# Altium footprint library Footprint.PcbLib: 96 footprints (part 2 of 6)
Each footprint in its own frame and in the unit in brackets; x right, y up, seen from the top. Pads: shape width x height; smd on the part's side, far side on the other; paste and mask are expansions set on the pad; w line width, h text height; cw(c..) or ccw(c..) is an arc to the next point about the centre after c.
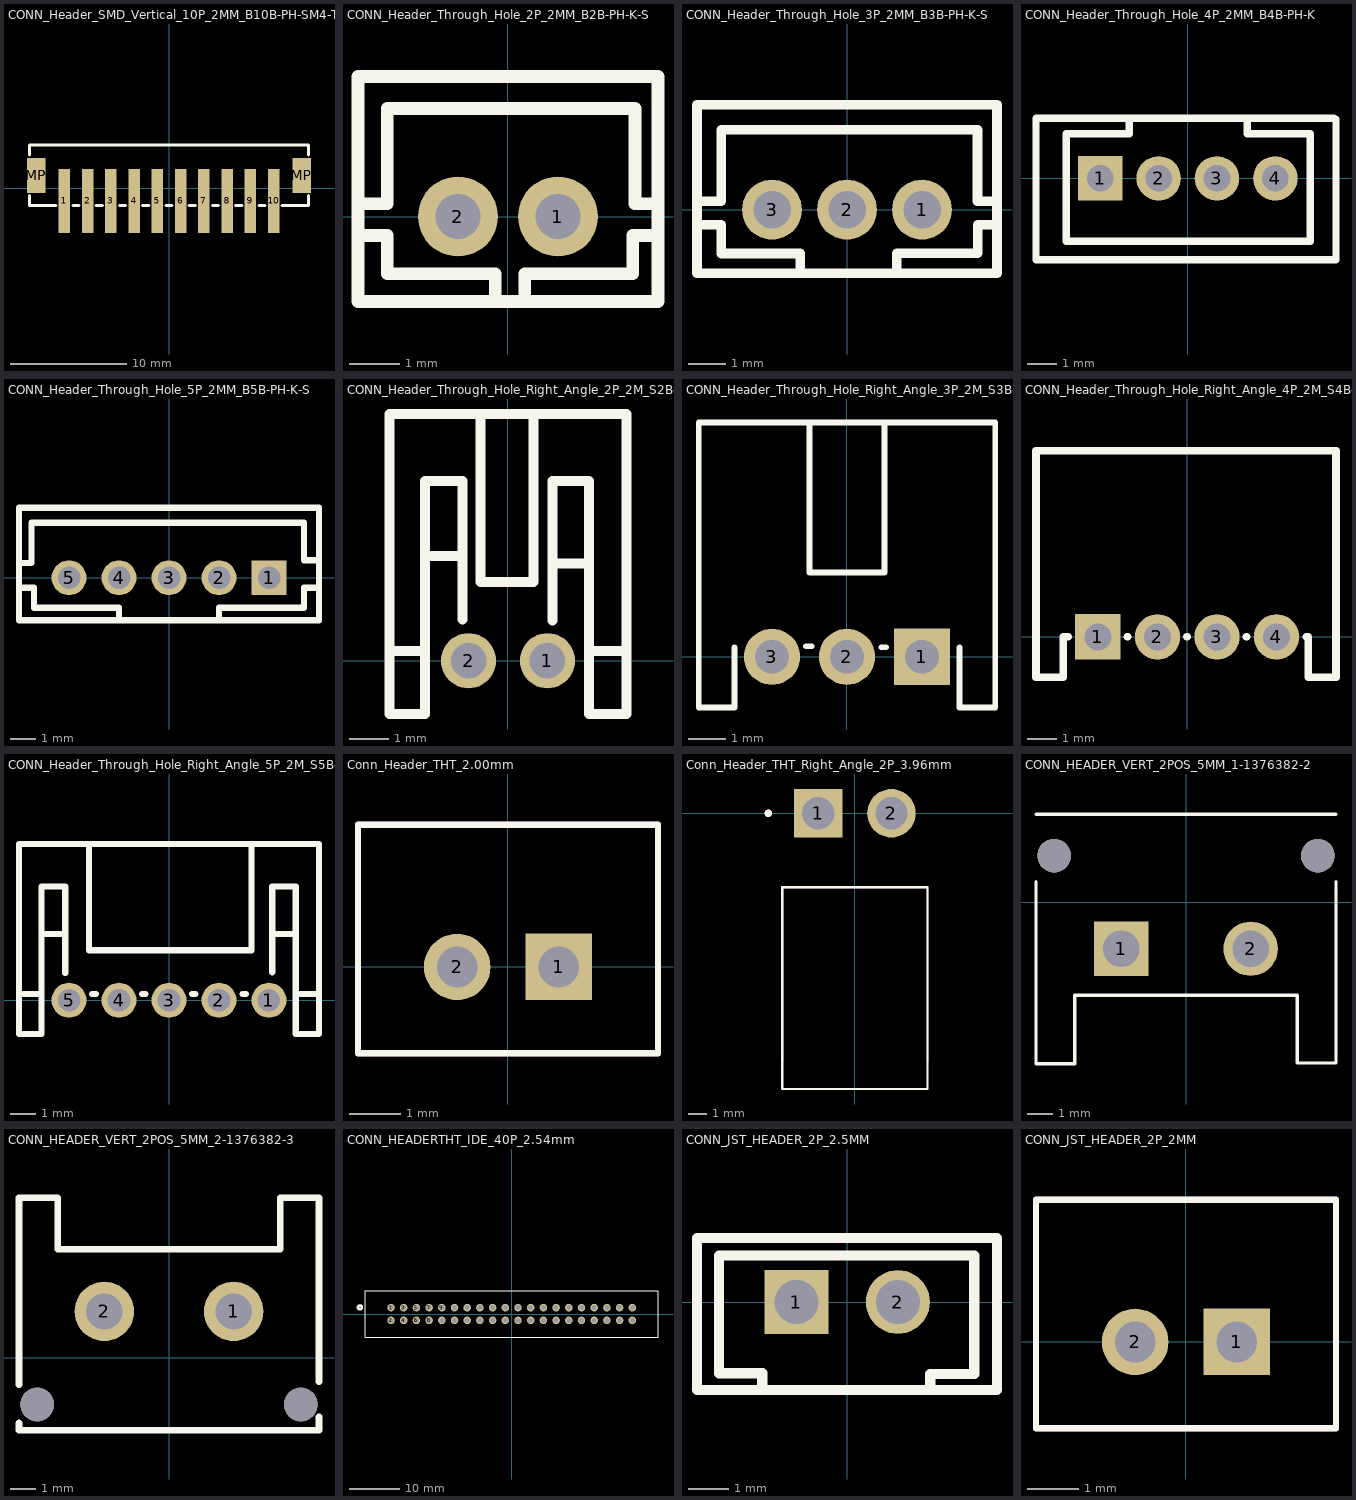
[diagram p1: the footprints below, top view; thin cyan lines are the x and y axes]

## CONN_Header_SMD_Vertical_10P_2MM_B10B-PH-SM4-TB [mm]
pads (12):
  rect 1x5.5 smd paste+0 mask+0.051: 1(-9,-1.099) 2(-7,-1.099) 3(-5,-1.099) 4(-3,-1.099) 5(-1,-1.099) 6(1,-1.099) 7(3.002,-1.101) 8(5.002,-1.101) 9(7,-1.099) 10(9,-1.099)
  rect 1.6x3 smd paste+0 mask+0.051: MP(-11.4,1.101) MP(11.4,1.101)
Top Overlay:
  lines w0.254: -12,-0.63 -12,-1.5 -11.094,-1.5 ; -12,2.832 -12,3.7 12,3.7 12,2.832 ; -11.2,-1.5 -9.731,-1.5 ; -8.269,-1.5 -7.731,-1.5 ; -6.269,-1.5 -5.731,-1.5 ; -4.269,-1.5 -3.731,-1.5 ; -2.269,-1.5 -1.731,-1.5 ; -0.269,-1.5 0.269,-1.5 ; 1.731,-1.5 2.271,-1.5 ; 3.733,-1.5 4.271,-1.5 ; 5.733,-1.5 6.269,-1.5 ; 7.731,-1.5 8.269,-1.5 ; 9.731,-1.5 12,-1.5 12,-0.63
3D body "CONN-TH_B10B-PH-SM4-TB-LF-SN.step": height 6.7, standoff 0, extent -11.975,-3.49 12.026,3.51

## CONN_Header_Through_Hole_2P_2MM_B2B-PH-K-S [mm]
pads (2):
  round 1.6 hole 0.9 paste+0 mask+0.051: 1(1,0) 2(-1,0)
Top Overlay:
  lines w0.254: -2.921,-0.381 -2.413,-0.381 -2.413,-1.143 -0.254,-1.143 -0.254,-1.651 ; -2.921,0.254 -2.413,0.254 -2.413,2.159 2.54,2.159 2.54,0.254 2.921,0.254 ; 0.333,-1.651 0.333,-1.143 2.492,-1.143 2.492,-0.381 3,-0.381 ; -3,-1.7 -3,2.8 3,2.8 3,-1.7 -3,-1.7
3D body "B2B-PH-K-S.STEP": height 6.1, standoff -3.3, extent -2.899,-1.767 3.001,2.733

## CONN_Header_Through_Hole_3P_2MM_B3B-PH-K-S [mm]
pads (3):
  round 1.6 hole 1 paste+0 mask+0.051: 1(2,0) 2(0,0) 3(-2,0)
Top Overlay:
  lines w0.254: -3.909,-0.408 -3.353,-0.408 -3.353,-1.17 -1.242,-1.17 -1.242,-1.678 ; -3.909,0.227 -3.353,0.227 -3.353,2.134 3.48,2.134 3.48,0.229 3.912,0.229 ; 1.324,-1.676 1.324,-1.168 3.483,-1.168 3.483,-0.406 3.991,-0.406 ; -4,-1.7 -4,2.8 4,2.8 4,-1.7 -4,-1.7
3D body "B3B-PH-K-SLFSN.STEP": height 6.2, standoff -3.2, extent -3.95,-1.666 3.95,2.834

## CONN_Header_Through_Hole_4P_2MM_B4B-PH-K [mil]
pads (4):
  rect 60x60 hole 36 paste+0 mask+2: 1(-118.11,0)
  round 60 hole 36 paste+0 mask+2: 2(-39.37,0) 3(39.37,0) 4(118.11,0)
Top Overlay:
  lines w10: -78.78,80 -78.78,60 -163.78,60 -163.78,-85 163.78,-85 ; 80,80 80,60 165,60 165,-85 ; 196.85,-110 -204.85,-110 -204.85,81.15 197.24,81.15 ; 200,-110 200,80
3D body "B4B-PH-K-S(LF)(SN)--3DModel-STEP-56544.STEP": height 240.16, standoff -129.92, extent -194.88,-107 194.88,70.16

## CONN_Header_Through_Hole_5P_2MM_B5B-PH-K-S [mm]
pads (5):
  rect 1.4x1.4 hole 0.9 paste+0 mask+0.051: 1(4,0)
  round 1.4 hole 0.9 paste+0 mask+0.051: 2(2,0) 3(0,0) 4(-2,0) 5(-4,0)
Top Overlay:
  lines w0.254: -6.002,-0.399 -5.4,-0.399 -5.4,-1.199 -1.999,-1.199 -1.999,-1.699 -2,-1.7 ; -6,0.6 -5.5,0.593 -5.5,2.2 5.4,2.2 5.4,0.701 6,0.701 ; 2,-1.7 1.999,-1.699 1.999,-1.199 5.4,-1.199 5.4,-0.399 6,-0.399 ; -6,-1.7 -6,2.8 6,2.8 6,-1.7 -6,-1.7
3D body "B5B-PH-K-S.STEP": height 6.2, standoff -3.2, extent -5.975,-1.691 5.925,2.809

## CONN_Header_Through_Hole_Right_Angle_2P_2M_S2B-PH-K-S [mm]
pads (2):
  round 1.4 hole 0.9 paste+0 mask+0.051: 1(1,0) 2(-1,0)
Top Overlay:
  lines w0.254: -2.108,0.25 -3,0.25 ; -2.1,0.25 -2.1,4.55 -1.15,4.55 -1.15,1.041 ; -2.1,2.65 -1.15,2.65 ; -2.1,0.25 -2.1,-1.35 -3,-1.35 -3,0.25 ; -0.7,6.25 -0.699,6.251 -0.699,1.999 0.65,1.999 0.65,6.251 ; 1.125,1.016 1.125,4.55 2.057,4.55 ; 1.143,2.464 2.032,2.464 ; 2.057,0.25 3,0.25 ; 2.057,4.521 2.057,-1.35 3,-1.35 3,0.25 ; -3,0.25 -3,6.25 3,6.25 3,0.25
3D body "S2B-PH-K-S.STEP": height 4.9, standoff -3.28, extent -3.026,-1.426 2.874,6.174

## CONN_Header_Through_Hole_Right_Angle_3P_2M_S3B-PH-K-S [mm]
pads (3):
  rect 1.5x1.5 hole 0.9 paste+0 mask+0.051: 1(2,0)
  round 1.5 hole 0.9 paste+0 mask+0.051: 2(0,0) 3(-2,0)
Top Overlay:
  lines w0.152: -3,0.25 -3,-1.35 -3.95,-1.35 -3.95,6.25 3.95,6.25 3.95,-1.35 3,-1.35 3,0.25 ; -1.092,0.279 -0.94,0.279 ; -1,6.25 -1,2.25 0.999,2.25 0.999,6.25 ; 0.914,0.254 1.041,0.254
Mechanical 15:
  region: 4,5.4 4,6.2 3.9,6.3 -3.9,6.3 -4,6.2 -4,5.6 -3.9,5.6 -3.9,6.2 3.9,6.2 3.9,5.4
3D body "S3B-PH-K-S.STEP": height 4.9, standoff -3.3, extent -3.95,-1.35 3.95,6.25

## CONN_Header_Through_Hole_Right_Angle_4P_2M_S4B-PH-K-S [mil]
pads (4):
  rect 60x60 hole 36 paste+0 mask+2: 1(-118.11,0)
  round 60 hole 36 paste+0 mask+2: 2(-39.37,0) 3(39.37,0) 4(118.11,0)
Top Overlay:
  lines w10: -157.21,0 -163.83,0 -163.83,-53.15 -200,-53.15 -200,246.06 196.85,246.06 ; -79.01,0 -78.47,0 ; -0.27,0 0.27,0 ; 78.47,0 79.01,0 ; 157.21,0 160,0 160,-53.15 196.85,-53.15 196.85,245
3D body "CONN-TH_4P-P2.00_S4B-PH-K-S.step": height 192.75, standoff -126.15, extent -198.05,-49 196.05,250.21

## CONN_Header_Through_Hole_Right_Angle_5P_2M_S5B-PH-K-S [mm]
pads (5):
  round 1.4 hole 0.9 paste+0 mask+0.051: 1(4,0) 2(2,0) 3(0,0) 4(-2,0) 5(-4,0)
Top Overlay:
  lines w0.254: -5.162,0.25 -6,0.25 ; -5.1,0.25 -5.1,4.55 -4.15,4.55 -4.15,1.088 ; -5.1,2.65 -4.15,2.65 ; -5.1,0.25 -5.1,-1.35 -6,-1.35 -6,0.25 ; -3.2,6.25 -3.2,2 3.3,2 3.3,6.25 ; -3.079,0.25 -2.927,0.25 ; -1.072,0.25 -0.945,0.25 ; 0.934,0.25 1.061,0.25 ; 2.941,0.25 3.068,0.25 ; 4.125,1.114 4.125,4.55 5.075,4.55 5.075,0.2 5.075,-1.35 6,-1.35 6,0.25 ; 4.125,2.65 5.075,2.65 ; 5.125,0.25 6,0.25 ; -6,0.25 -6,6.25 6,6.25 6,0.25
3D body "CONN-TH_S5B-PH-K-S-LF-SN.step": height 4.9, standoff -3.3, extent -5.969,-1.463 5.932,6.137

## Conn_Header_THT_2.00mm [mm]
pads (2):
  rect 1.308x1.308 / inner round 1.308 / far side rect 1.308x1.308 hole 0.8: 1(1,0)
  round 1.308 hole 0.8: 2(-1,0)
Top Overlay:
  lines w0.127: -2.95,-1.7 -2.95,2.8 2.95,2.8 2.95,-1.7 -2.95,-1.7
Mechanical 13:
  lines w0.127: -2.95,-1.7 2.95,-1.7 2.95,2.8 -2.95,2.8 -2.95,-1.7
3D body "step_temp.STEP": height 6, standoff -3.4, extent -2.95,-1.7 2.95,2.8

## Conn_Header_THT_Right_Angle_2P_3.96mm [mm]
pads (2):
  rect 2.625x2.625 / inner round 2.625 / far side rect 2.625x2.625 hole 1.75: 1(-1.98,0)
  round 2.625 hole 1.75: 2(1.98,0)
Top Overlay:
  circle w0.2: c-4.68,0 r0.1
  lines w0.127: -3.93,-14.91 3.93,-14.91 3.93,-4 -3.93,-4 -3.93,-14.91
Mechanical 13:
  circle w0.2: c-4.68,0 r0.1
  lines w0.127: -3.93,-13.4 -3.93,-4 3.93,-4 3.93,-13.4
3D body "B2PS-VH -LF--SN---3DModel-STEP-56544.STEP": height 8.5, standoff -3.6, extent -3.981,-14.925 3.879,0.545

## CONN_HEADER_VERT_2POS_5MM_1-1376382-2 [mm]
pads (4):
  rect 2.1x2.1 hole 1.4: 1(-2.5,-1.8)
  round 2.1 hole 1.4: 2(2.5,-1.8)
  round 1.3 hole 1.3 unplated: ""(-5.1,1.8) ""(5.1,1.8)
Top Overlay:
  lines w0.127: -5.8,0.8 -5.8,-6.248 -4.3,-6.248 -4.3,-3.6 4.3,-3.6 4.3,-6.223 5.8,-6.223 5.8,0.8 ; -5.8,3.4 5.8,3.4
3D body "c-1-1376382-2-d-3d.stp": height 14.2, standoff -3.4, extent -5.791,-6.196 5.809,3.404

## CONN_HEADER_VERT_2POS_5MM_2-1376382-3 [mm]
pads (4):
  round 2.3 hole 1.4 paste+0 mask+0.051: 1(2.5,1.8) 2(-2.5,1.8)
  round 1.3 hole 1.3 unplated paste+0: ""(-5.1,-1.8) ""(5.1,-1.8)
Top Overlay:
  lines w0.254: -5.8,-2.515 -5.8,-2.8 5.8,-2.8 5.8,-2.268 ; -5.8,-1.041 -5.8,6.2 -4.3,6.2 -4.3,4.2 4.3,4.2 4.3,6.2 5.8,6.2 5.8,-0.914
Mechanical 15:
  circle w0.55: c-5.1,-1.8 r0.275
  circle w0.55: c5.1,-1.8 r0.275
3D body "2-1376382-3.stp": height 14.2, standoff -3.4, extent -5.791,-3.353 5.809,6.247

## CONN_HEADERTHT_IDE_40P_2.54mm [mil]
pads (40):
  round 59 / inner round 60 / far side round 59 hole 39 paste-29.5 mask+0: 1(-950,50) 2(-950,-50) 3(-850,50) 4(-850,-50) 5(-750,50) 6(-750,-50) 7(-650,50) 8(-650,-50) 9(-550,50) 10(-550,-50) 11(-450,50) 12(-450,-50) 13(-350,50) 14(-350,-50) 15(-250,50) 16(-250,-50) 17(-150,50) 18(-150,-50) 19(-50,50) 20(-50,-50) 21(50,50) 22(50,-50) 23(150,50) 24(150,-50) 25(250,50) 26(250,-50) 27(350,50) 28(350,-50) 29(450,50) 30(450,-50) 31(550,50) 32(550,-50) 33(650,50) 34(650,-50) 35(750,50) 36(750,-50) 37(850,50) 38(850,-50) 39(950,50) 40(950,-50)
Top Overlay:
  circle w20: c-1195,52 r15
  lines w6: -1152.5,-183.87 -1152.5,184.13 1152.5,184.13 1152.5,-183.87 -1152.5,-183.87
3D body "sbh11-pbpc-d20-st-bk.stp": height 354.33, standoff -122.05, extent -1145.23,-171.82 1150.05,186.45

## CONN_JST_HEADER_2P_2.5MM [mm]
pads (2):
  rect 1.6x1.6 hole 1.1 paste+0 mask+0.051: 1(-1.27,0)
  round 1.6 hole 1.1 paste+0 mask+0.051: 2(1.27,0)
Top Overlay:
  lines w0.254: -3.755,1.601 -3.755,-2.199 3.745,-2.199 ; -3.75,1.6 3.75,1.6 3.75,-2.2 ; -2.12,-2.2 -2.121,-2.2 -2.121,-1.781 -3.2,-1.781 -3.2,1.161 3.18,1.161 3.18,-1.801 2.08,-1.801 2.08,-2.159
Mechanical 15:
  lines w0.003: 1.394,-0.173 1.395,-0.172
3D body "JST-B2B-EH-A.STEP": height 6.1, standoff -3.1, extent -3.77,-2.2 3.73,1.6

## CONN_JST_HEADER_2P_2MM [mm]
pads (2):
  rect 1.308x1.308 / inner round 1.308 / far side rect 1.308x1.308 hole 0.8: 1(1,0)
  round 1.308 hole 0.8: 2(-1,0)
Top Overlay:
  lines w0.127: -2.95,-1.7 2.95,-1.7 2.95,2.8 -2.95,2.8 -2.95,-1.7
Mechanical 13:
  lines w0.127: -2.95,-1.7 -2.95,2.8 2.95,2.8 2.95,-1.7 -2.95,-1.7
3D body "step_temp.STEP": height 6, standoff -3.4, extent -2.95,-1.7 2.95,2.8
